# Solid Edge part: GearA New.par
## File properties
Author: vinurabandara
Template: iso metric part.par
Last saved by: Chalangana Oshan
Revision: 37
Application: Solid Edge
Username: Nimesh.N
Density: 7250.000 kg/m^3
Accuracy: 0.990
Material: Iron:0.6025 , EN-GJL-250
Face Style: Gray
Fill Style: ANSI31(Iron)
Grouping: Iron\Gray Cast Iron
LibraryName: Materials-DIN
Coef. of Thermal Exp: 1.05e-05
Thermal Conductivity: 58.0
Specific Heat: 460.0
Modulus of Elasticity: 120000003072.0
Poisson's Ratio: 0.26
Yield Stress: 165593984.0
Ultimate Stress: 250000000.0
Elongation: 0.0
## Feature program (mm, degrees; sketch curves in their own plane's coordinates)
sketch for "unnamed Protrusion 1" plane through (0, 0, 0) normal (0, 0, 1) x-axis (1, 0, 0)
  circle centre (0, 0) radius 235
extrude "unnamed Protrusion 1" add finite 130 along -normal
sketch used by "unnamed Cutout 1" plane through (0, 0, 0) normal (0, 0, 1) x-axis (1, 0, 0)
  line (0, 0) -> (-16.3928, 234.4276)
  line (0, 0) -> (-13.664, 234.6024)
  line (0, 0) -> (-40.8073, 231.4298)
  line (-3.7086, 212.4676) -> (3.7086, 212.4676)
  arc centre (-62.2756, 199.4326) radius 60 from (-13.664, 234.6024) to (-3.7086, 212.4676) cw
  arc centre (62.2756, 199.4326) radius 60 from (13.664, 234.6024) to (3.7086, 212.4676) ccw
extrude "unnamed Cutout 1" cut through along -normal
pattern "unnamed Pattern 1" of "unnamed Cutout 1"
pattern "unnamed Pattern 2"
sketch for "unnamed Cutout 2" plane through (0, 0, 0) normal (0, 0, 1) x-axis (0.034899, 0.999391, 0)
extrude "unnamed Cutout 2" cut through along -normal
sketch for "unnamed Cutout 3" plane through (0, -0.1988, -130) normal (0, 0, -1) x-axis (-0.913545, -0.406737, 0)
  line (-10.0809, 37.5816) -> (-10.0809, 0.1816)
  line (-10.0809, 0.1816) -> (9.9191, 0.1816)
  line (9.9191, 0.1816) -> (9.9191, 37.5816)
  line (9.9191, 37.5816) -> (-10.0809, 37.5816)
extrude "unnamed Cutout 3" cut through along -normal
sketch for "unnamed Cutout 4" #1 plane through (0, 0, 0) normal (0, 0, 1) x-axis (0.034899, 0.999391, 0)
  circle centre (0, 0) radius 85
sketch for "unnamed Cutout 4" #2 plane through (0, 0, 0) normal (0, 0, 1) x-axis (0.034899, 0.999391, 0)
  circle centre (0, 0) radius 191.25
extrude "unnamed Cutout 4" cut finite 35 along -normal
mirror "unnamed Mirror 1" of "unnamed Cutout 4"
pattern "unnamed Pattern 3"
sketch for "unnamed Cutout 5" plane through (0, 0, -35) normal (0, 0, 1) x-axis (1, 0, 0)
extrude "unnamed Cutout 5" cut through along -normal
pattern "unnamed Pattern 4" of "unnamed Cutout 5"
pattern "unnamed Pattern 5"
fillet "unnamed Round 1"
fillet "Round_3" radius 10
Other named dimensions: "ExtrudedSurface_3": FiniteDepth = 130 mm
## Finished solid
Body 1: sheet body, 1 face, 2 edges, 0 vertices.
  Faces by surface: cylinder 1
  Edges by curve: circle 2
Body 2: solid body, 226 faces, 656 edges, 432 vertices.
  Faces by surface: cylinder 164, plane 62
  Edges by curve: circle 328, line 328
Bounding box of the edges (mm): 469.873 x 469.602 x 130.000, from (-234.9364, -235, -130) to (234.9364, 234.6024, 0).
Cylindrical faces by radius (mm): R10 x16, R32.5 x1, R60 x90, R85 x2, R102 x4, R176.375 x4, R191.25 x2, R225 x1, R235 x45
Planar faces by outward normal: +y 1, +z 3, -z 3, oblique 55
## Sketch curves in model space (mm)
line (0, 0, -130) -> (-13.2189, 29.6902, -130)
line (-4.0835, 33.7576, -130) -> (-22.3544, 25.6229, -130)
line (-9.1355, -4.0674, -130) -> (-24.3474, 30.0992, -130)
line (-24.3474, 30.0992, -130) -> (-6.0765, 38.234, -130)
line (-6.0765, 38.234, -130) -> (9.1355, 4.0674, -130)
line (9.1355, 4.0674, -130) -> (-9.1355, -4.0674, -130)
line (0, 0, 0) -> (-40.8073, 231.4298, 0)
line (0, 0, 0) -> (-16.3928, 234.4276, 0)
line (0, 0, 0) -> (4.1013, 234.9642, 0)
line (0, 0, 0) -> (-4.1013, 234.9642, 0)
arc centre (62.2756, 199.4326, 0) radius 60 from (13.664, 234.6024, 0) through (7.5554, 224.0437, 0) to (3.7086, 212.4676, 0)
line (-3.7086, 212.4676, 0) -> (3.7086, 212.4676, 0)
arc centre (-62.2756, 199.4326, 0) radius 60 from (-13.664, 234.6024, 0) through (-7.5554, 224.0437, 0) to (-3.7086, 212.4676, 0)
line (0, 0, 0) -> (-13.664, 234.6024, 0)
circle centre (0, 0, 0) radius 235
circle centre (0, 0, 0) radius 225
circle centre (0, 0, 0) radius 212.5
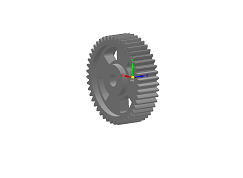
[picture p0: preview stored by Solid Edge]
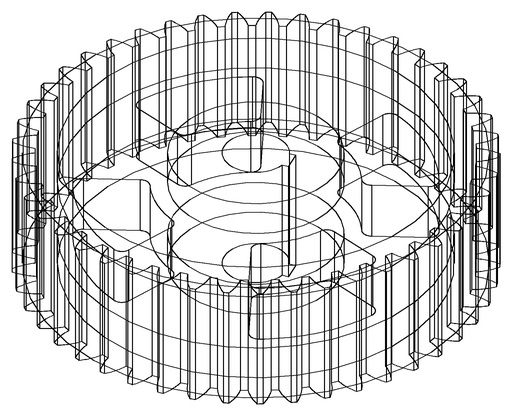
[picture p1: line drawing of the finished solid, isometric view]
